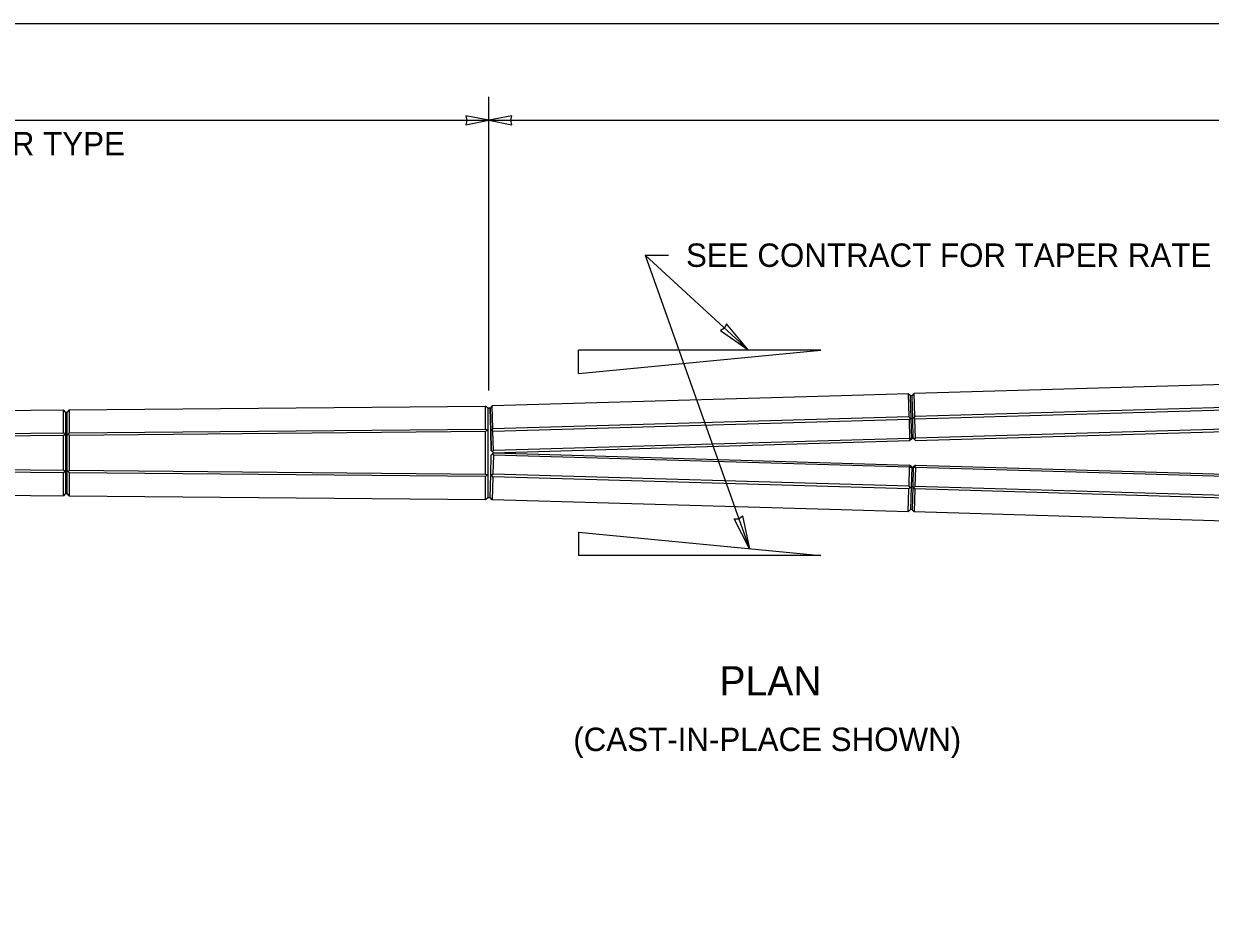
# Model space of a CAD drawing. Extents: x 99862 to 103151, y 100000 to 102076.
# Drawn here: x 100993 to 101804, y 101460 to 102076 of the extents above; entities that cross this region are included whole.
import ezdxf

# ---------------------------------------------------------------- set-up
doc = ezdxf.new("R2010")
doc.units = 0
for name, color, linetype in [('Level 1', 7, 'Continuous'), ('Level 15', 7, 'Continuous'), ('Level 2', 7, 'Continuous'), ('Level 20', 7, 'Continuous'), ('Level 25', 7, 'Continuous'), ('Level 3', 7, 'Continuous')]:
    doc.layers.add(name, color=color, linetype=linetype)

msp = doc.modelspace()

# ---------------------------------------------------------------- linework, layer by layer
at = {"layer": 'Level 1'}
msp.add_lwpolyline([(99862, 99999.5), (103151, 99999.5), (103151, 102075.5), (99862, 102075.5)], close=True, dxfattribs=at)
at = {"layer": 'Level 15'}
for p, q in [((101310.75, 101824.65), (101310.75, 102025.5)), ((100445.23, 102009.49), (101310.74, 102009.49)), ((101310.74, 102009.49), (102999.74, 102009.49)), ((101417.45, 101917.26), (101433.45, 101917.26)), ((101417.45, 101917.26), (101487.84, 101852.53)), ((101372, 101836.41), (101537.52, 101852.41)), ((101537.52, 101852.41), (101372, 101852.41)), ((101372, 101836.41), (101372, 101852.41)), ((101372, 101727.89), (101537.52, 101711.89)), ((101372, 101727.89), (101372, 101711.89)), ((101537.52, 101711.89), (101372, 101711.89))]:
    msp.add_line(p, q, dxfattribs=at)
for points in [[(101310.74, 102009.49), (101295.02, 102012.58), (101295.75, 102009.49), (101295.02, 102006.41)], [(101310.74, 102009.49), (101326.47, 102006.41), (101325.74, 102009.49), (101326.47, 102012.58)], [(101487.84, 101852.53), (101473.11, 101870.23), (101471.86, 101867.32), (101469.06, 101865.84)], [(101488.8, 101716.6), (101478.35, 101737.11), (101481.52, 101737.11), (101483.98, 101739.11)]]:
    msp.add_lwpolyline(points, close=True, dxfattribs=at)
msp.add_lwpolyline([(101417.45, 101917.26), (101488.8, 101716.6)], dxfattribs=at)
at = {"layer": 'Level 2'}
for p, q in [((101885.24, 101830.88), (101601.36, 101822.6)), ((101551.38, 101821.14), (101312.98, 101814.19)), ((101597.36, 101822.48), (101551.38, 101821.14)), ((101598.9, 101821), (101597.36, 101822.48)), ((101597.36, 101822.48), (101597.82, 101806.77)), ((101599.9, 101821.03), (101598.9, 101821)), ((101599.36, 101805.29), (101598.9, 101821)), ((101599.9, 101821.03), (101601.36, 101822.6)), ((101600.36, 101805.32), (101599.9, 101821.03)), ((101601.82, 101806.89), (101601.36, 101822.6)), ((100735.98, 101808.83), (101019.98, 101811.46)), ((101021.48, 101809.98), (101019.98, 101811.46)), ((101021.48, 101809.98), (101022.48, 101809.99)), ((101023.98, 101811.5), (101022.48, 101809.99)), ((101023.98, 101811.5), (101308.48, 101814.13)), ((101309.98, 101812.65), (101308.48, 101814.13)), ((101312.98, 101814.19), (101311.53, 101812.65)), ((101311.53, 101812.65), (101311.98, 101796.91)), ((101313.44, 101798.48), (101312.98, 101814.19)), ((101885.7, 101815.17), (101601.82, 101806.89)), ((101885.75, 101813.39), (101601.87, 101805.11)), ((101597.82, 101806.77), (101313.44, 101798.48)), ((101597.87, 101804.99), (101313.49, 101796.7)), ((101597.82, 101806.77), (101598.58, 101805.9)), ((101598.58, 101805.9), (101597.87, 101804.99)), ((101597.87, 101804.99), (101598.25, 101792)), ((101598.58, 101805.9), (101599.36, 101805.29)), ((101600.36, 101805.32), (101599.36, 101805.29)), ((101599.75, 101792.04), (101599.36, 101805.29)), ((101601.11, 101805.98), (101600.36, 101805.32)), ((101600.75, 101792.07), (101600.36, 101805.32)), ((101601.82, 101806.89), (101601.11, 101805.98)), ((101601.11, 101805.98), (101601.87, 101805.11)), ((101602.25, 101792.11), (101601.87, 101805.11)), ((101312.73, 101797.57), (101311.98, 101796.91)), ((101311.98, 101796.91), (101312.37, 101783.66)), ((101313.44, 101798.48), (101312.73, 101797.57)), ((101312.73, 101797.57), (101313.49, 101796.7)), ((101313.87, 101783.71), (101313.49, 101796.7)), ((101886.13, 101800.39), (101602.25, 101792.11)), ((101602.29, 101790.61), (101886.17, 101798.89)), ((101598.25, 101792), (101313.87, 101783.71)), ((101313.91, 101782.21), (101598.29, 101790.5)), ((101599.02, 101791.27), (101598.25, 101792)), ((101598.29, 101790.5), (101599.75, 101792.04)), ((101599.02, 101791.27), (101598.29, 101790.5)), ((101599.75, 101792.04), (101599.02, 101791.27)), ((101599.75, 101792.04), (101600.75, 101792.07)), ((101600.75, 101792.07), (101602.29, 101790.61)), ((101600.75, 101792.07), (101601.52, 101791.34)), ((101601.52, 101791.34), (101602.25, 101792.11)), ((101602.29, 101790.61), (101601.52, 101791.34)), ((101311.98, 101767.38), (101312.37, 101780.63)), ((101312.37, 101783.66), (101313.14, 101782.93)), ((101312.37, 101780.63), (101313.14, 101781.36)), ((101313.14, 101782.93), (101313.87, 101783.71)), ((101313.91, 101782.21), (101313.14, 101782.93)), ((101313.91, 101782.09), (101313.14, 101781.36)), ((101313.14, 101781.36), (101313.87, 101780.59)), ((101313.87, 101780.59), (101313.49, 101767.59)), ((101598.25, 101772.3), (101313.87, 101780.59)), ((101313.91, 101782.09), (101598.29, 101773.8)), ((101597.87, 101759.3), (101598.25, 101772.3)), ((101599.02, 101773.02), (101598.25, 101772.3)), ((101599.75, 101772.25), (101598.29, 101773.8)), ((101599.02, 101773.02), (101598.29, 101773.8)), ((101599.75, 101772.25), (101599.02, 101773.02)), ((101599.75, 101772.25), (101599.36, 101759)), ((101599.75, 101772.25), (101600.75, 101772.22)), ((101600.75, 101772.22), (101600.36, 101758.97)), ((101602.29, 101773.68), (101600.75, 101772.22)), ((101600.75, 101772.22), (101601.52, 101772.95)), ((101602.29, 101773.68), (101601.52, 101772.95)), ((101601.52, 101772.95), (101602.25, 101772.18)), ((101602.25, 101772.18), (101601.87, 101759.19)), ((101886.13, 101763.9), (101602.25, 101772.18)), ((101602.29, 101773.68), (101886.17, 101765.4)), ((101311.53, 101751.65), (101311.98, 101767.38)), ((101312.73, 101766.73), (101311.98, 101767.38)), ((101312.73, 101766.73), (101313.49, 101767.59)), ((101313.44, 101765.81), (101312.73, 101766.73)), ((101313.44, 101765.81), (101312.98, 101750.1)), ((101597.82, 101757.52), (101313.44, 101765.81)), ((101597.87, 101759.3), (101313.49, 101767.59)), ((100735.98, 101755.46), (101019.98, 101752.83)), ((101021.48, 101754.32), (101019.98, 101752.83)), ((101021.48, 101754.32), (101022.48, 101754.31)), ((101023.98, 101752.8), (101022.48, 101754.31)), ((101023.98, 101752.8), (101308.48, 101750.16)), ((101597.36, 101741.81), (101597.82, 101757.52)), ((101597.82, 101757.52), (101598.58, 101758.39)), ((101598.58, 101758.39), (101597.87, 101759.3)), ((101598.58, 101758.39), (101599.36, 101759)), ((101599.36, 101759), (101598.9, 101743.3)), ((101600.36, 101758.97), (101599.36, 101759)), ((101600.36, 101758.97), (101599.9, 101743.27)), ((101601.11, 101758.32), (101600.36, 101758.97)), ((101601.11, 101758.32), (101601.87, 101759.19)), ((101601.82, 101757.41), (101601.11, 101758.32)), ((101601.82, 101757.41), (101601.36, 101741.7)), ((101885.7, 101749.13), (101601.82, 101757.41)), ((101885.75, 101750.91), (101601.87, 101759.19)), ((101308.48, 101750.16), (101309.98, 101751.65)), ((101312.98, 101750.1), (101311.53, 101751.65)), ((101551.38, 101743.15), (101312.98, 101750.1)), ((101597.36, 101741.81), (101551.38, 101743.15)), ((101598.9, 101743.3), (101597.36, 101741.81)), ((101599.9, 101743.27), (101598.9, 101743.3)), ((101599.9, 101743.27), (101601.36, 101741.7)), ((101885.24, 101733.42), (101601.36, 101741.7))]:
    msp.add_line(p, q, dxfattribs=at)
at = {"layer": 'Level 25'}
for points in [[(101602.25, 101792.11), (101598.25, 101792)], [(101598.25, 101772.3), (101602.25, 101772.18)]]:
    msp.add_lwpolyline(points, dxfattribs=at)
at = {"layer": 'Level 3'}
for p, q in [((101019.98, 101795.74), (101019.98, 101811.46)), ((101021.48, 101809.98), (101021.48, 101794.23)), ((101022.48, 101794.24), (101022.48, 101809.99)), ((101023.98, 101811.5), (101023.98, 101795.78)), ((101308.48, 101798.41), (101308.48, 101814.13)), ((101311.53, 101812.65), (101309.98, 101812.65)), ((101309.98, 101812.65), (101309.98, 101796.91)), ((101309.98, 101812.65), (101309.98, 101796.91)), ((101309.98, 101812.65), (101311.53, 101812.65)), ((101311.98, 101796.91), (101311.53, 101812.65)), ((100735.98, 101793.11), (101019.98, 101795.74)), ((101019.98, 101793.96), (100735.98, 101791.33)), ((101019.98, 101795.74), (101020.72, 101794.86)), ((101020.72, 101794.86), (101019.98, 101793.96)), ((101019.98, 101770.33), (101019.98, 101793.96)), ((101021.48, 101794.23), (101020.72, 101794.86)), ((101021.48, 101794.23), (101022.48, 101794.24)), ((101021.48, 101794.23), (101021.48, 101770.06)), ((101023.24, 101794.88), (101022.48, 101794.24)), ((101022.48, 101770.05), (101022.48, 101794.24)), ((101023.98, 101795.78), (101023.24, 101794.88)), ((101023.24, 101794.88), (101023.98, 101794)), ((101023.98, 101795.78), (101308.48, 101798.41)), ((101308.48, 101796.63), (101023.98, 101794)), ((101023.98, 101794), (101023.98, 101770.3)), ((101309.22, 101797.53), (101308.48, 101798.41)), ((101308.48, 101796.63), (101309.22, 101797.53)), ((101308.48, 101767.66), (101308.48, 101796.63)), ((101309.22, 101797.53), (101309.98, 101796.91)), ((101309.98, 101796.91), (101309.98, 101767.39)), ((101309.98, 101796.91), (101309.98, 101767.39)), ((101312.37, 101783.66), (101311.98, 101796.91)), ((101311.98, 101767.38), (101312.37, 101780.63)), ((101313.14, 101782.93), (101312.37, 101783.66)), ((101312.37, 101780.63), (101313.14, 101781.36)), ((101313.91, 101782.21), (101313.14, 101782.93)), ((101313.14, 101781.36), (101313.91, 101782.09)), ((101313.91, 101782.09), (101313.91, 101782.21)), ((101313.91, 101782.21), (101313.91, 101782.09)), ((100735.98, 101772.96), (101019.98, 101770.33)), ((101019.98, 101768.55), (100735.98, 101771.18)), ((101019.98, 101770.33), (101020.72, 101769.44)), ((101020.72, 101769.44), (101019.98, 101768.55)), ((101021.48, 101770.06), (101020.72, 101769.44)), ((101021.48, 101770.06), (101021.48, 101754.32)), ((101021.48, 101770.06), (101022.48, 101770.05)), ((101022.48, 101754.31), (101022.48, 101770.05)), ((101023.24, 101769.41), (101022.48, 101770.05)), ((101023.98, 101770.3), (101023.24, 101769.41)), ((101023.24, 101769.41), (101023.98, 101768.51)), ((101023.98, 101770.3), (101308.48, 101767.66)), ((101019.98, 101752.83), (101019.98, 101768.55)), ((101023.98, 101768.51), (101023.98, 101752.8)), ((101308.48, 101765.88), (101023.98, 101768.51)), ((101309.22, 101766.76), (101308.48, 101767.66)), ((101308.48, 101765.88), (101309.22, 101766.76)), ((101308.48, 101750.16), (101308.48, 101765.88)), ((101309.98, 101767.39), (101309.22, 101766.76)), ((101309.98, 101767.39), (101309.98, 101751.65)), ((101309.98, 101767.39), (101309.98, 101751.65)), ((101311.53, 101751.65), (101311.98, 101767.38)), ((101309.98, 101751.65), (101311.53, 101751.65)), ((101309.98, 101751.65), (101311.53, 101751.65))]:
    msp.add_line(p, q, dxfattribs=at)

# ---------------------------------------------------------------- texts
at = {"layer": 'Level 20'}
for s, height, p in [('LENGTH VARIES PER BARRIER TYPE', 16, (100677.94, 101985.49)), ('SEE CONTRACT FOR TAPER RATE', 16, (101445.45, 101909.26)), ('PLAN', 20, (101468.23, 101616.26)), ('(CAST-IN-PLACE SHOWN)', 16, (101368.42, 101578.26))]:
    msp.add_text(s, height=height, dxfattribs=at).set_placement(p)

doc.saveas('drawing.dxf')
